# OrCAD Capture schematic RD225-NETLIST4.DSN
size A3
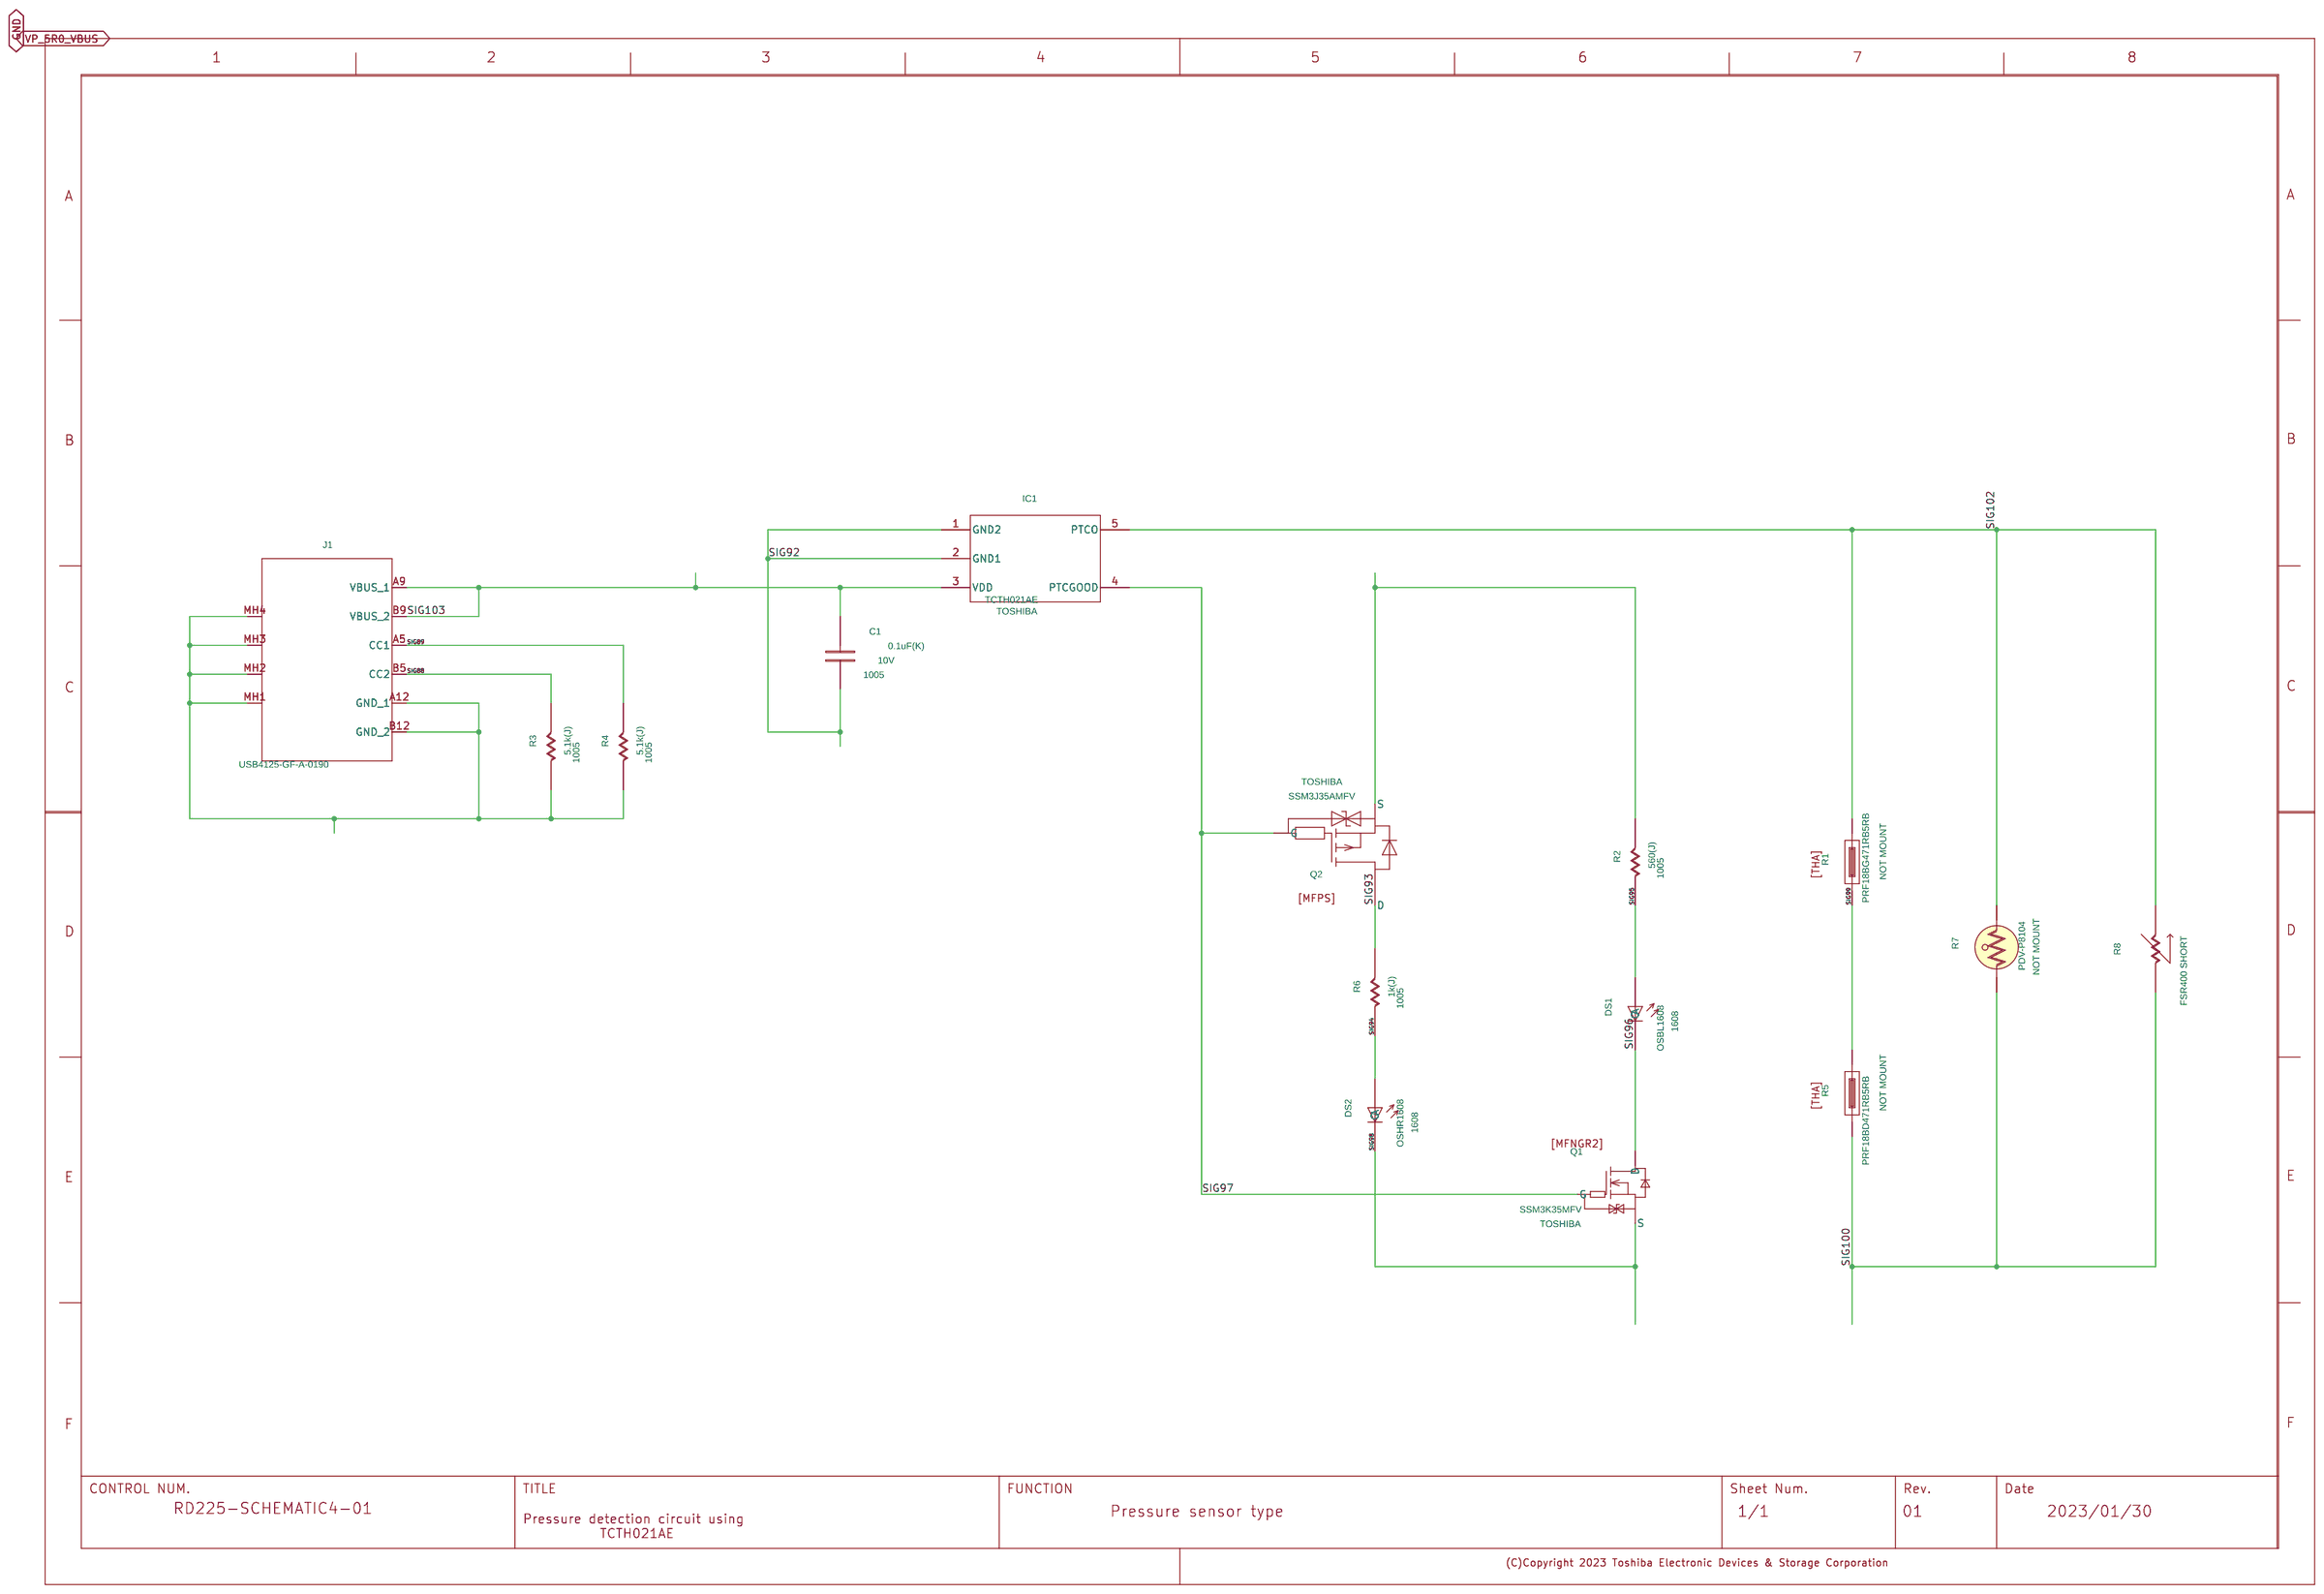
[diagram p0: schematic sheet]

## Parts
C1  C
DS1  LED
DS2  LED
IC1  TCTH021AE
J1  USB4125-GF-A-0190
Q1  MFNGR2
Q2  MFPS
R1  THA
R2  R
R3  R
R4  R
R5  THA
R6  R
R7  HM-ERTJ0P473
R8  FSR400
U?#1  WAKU_DEF100

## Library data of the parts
C1 = C: SIZECODESMD: 1005; VAL1: 0.1uF(K); VAL2: 10V
DS1 = LED: SIZECODESMD: 1608; VAL1: OSBL1608; VAL3: OSBL1608
DS2 = LED: SIZECODESMD: 1608; VAL1: OSHR1608; VAL3: OSHR1608
IC1 = TCTH021AE: USERCOMPTEXT3: TOSHIBA
J1 = USB4125-GF-A-0190
Q1 = MFNGR2: COMP: SSM3K35MFV; USERCOMPTEXT3: TOSHIBA; VAL1: SSM3K35MFV; VAL3: SSM3K35MFV
Q2 = MFPS: COMP: SSM3J35AMFV; USERCOMPTEXT3: TOSHIBA; VAL1: SSM3J35AMFV; VAL3: SSM3J35AMFV
R1 = THA: COMP: PRF18BG471RB5RB; NOTMOUNT: NOT MOUNT; VAL1: PRF18BG471RB5RB; VAL3: PRF18BG471RB5RB
R2 = R: SIZECODESMD: 1005; VAL1: 560(J); VAL2: 100mW
R3 R4 = R: SIZECODESMD: 1005; VAL1: 5.1k(J); VAL2: 100mW
R5 = THA: COMP: PRF18BD471RB5RB; NOTMOUNT: NOT MOUNT; OLDCOMPONENTID: 399; VAL1: PRF18BD471RB5RB; VAL3: PRF18BD471RB5RB
R6 = R: SIZECODESMD: 1005; VAL1: 1k(J); VAL2: 100mW
R7 = HM-ERTJ0P473: COMP: CDS; NOTMOUNT: NOT MOUNT; VAL1: PDV-P8104; VAL3: PDV-P8104
R8 = FSR400: COMP: FSR400_SHORT; VAL1: FSR400 SHORT; VAL3: FSR400 SHORT
U?#1 = WAKU_DEF100: DATE: 2023/01/30; DRAWINGNUMBER: RD225-SCHEMATIC4-01; FUNCTION: Pressure sensor type; REVISION: 01; SAVEAREA0: 22200,72372,612276,319236; SAVECOUNT: 7; SHEETNUMBER: 1/1; TITLE: Pressure detection circuit using / TCTH021AE; UPDATEDATE: 2023/01/30; UPDATETIME: 17:48:40; UPDATEUSER: PS4_common_PC

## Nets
GND: C1.1 DS2.2(C) IC1.1(GND2) IC1.2(GND1) J1.A12(GND_1) J1.B12(GND_2) J1.MH1 J1.MH2 J1.MH3 J1.MH4 Q1.2(S) R3.1 R4.1 R5.1 R7.2 R8.1
SIG88: J1.B5(CC2) R3.2
SIG89: J1.A5(CC1) R4.2
SIG93: Q2.3(D) R6.2
SIG94: DS2.1(A) R6.1
SIG95: DS1.1(A) R2.1
SIG96: DS1.2(C) Q1.3(D)
SIG97: IC1.4(PTCGOOD) Q1.1(G) Q2.1(G)
SIG99: R1.1 R5.2
SIG102: IC1.5(PTCO) R1.2 R7.1 R8.2
VP_5R0_VBUS: C1.2 IC1.3(VDD) J1.A9(VBUS_1) J1.B9(VBUS_2) Q2.2(S) R2.2
